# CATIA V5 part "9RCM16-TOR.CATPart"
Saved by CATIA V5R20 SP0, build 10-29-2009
Part number: 9RCM16-TOR
Revision: ANY
Definition: UNKNOWN
Nomenclature: 9RCM16-TOR
Source: Unknown
Bounding box of the stored display mesh (mm): x -5.85 to 5.85, y 0 to 16.5, z -6 to 6
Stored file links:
  C:\Users\Utente\Desktop\IO LAVORO\3D X SITO CF\CUMSA\3D files RCM\RCM 163808\9RCM16-TOR.CATPart
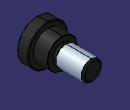
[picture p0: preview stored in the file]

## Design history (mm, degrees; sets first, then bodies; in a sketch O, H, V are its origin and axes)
Body1 "Redondeo1" (main body)
  Solid1: solid without history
